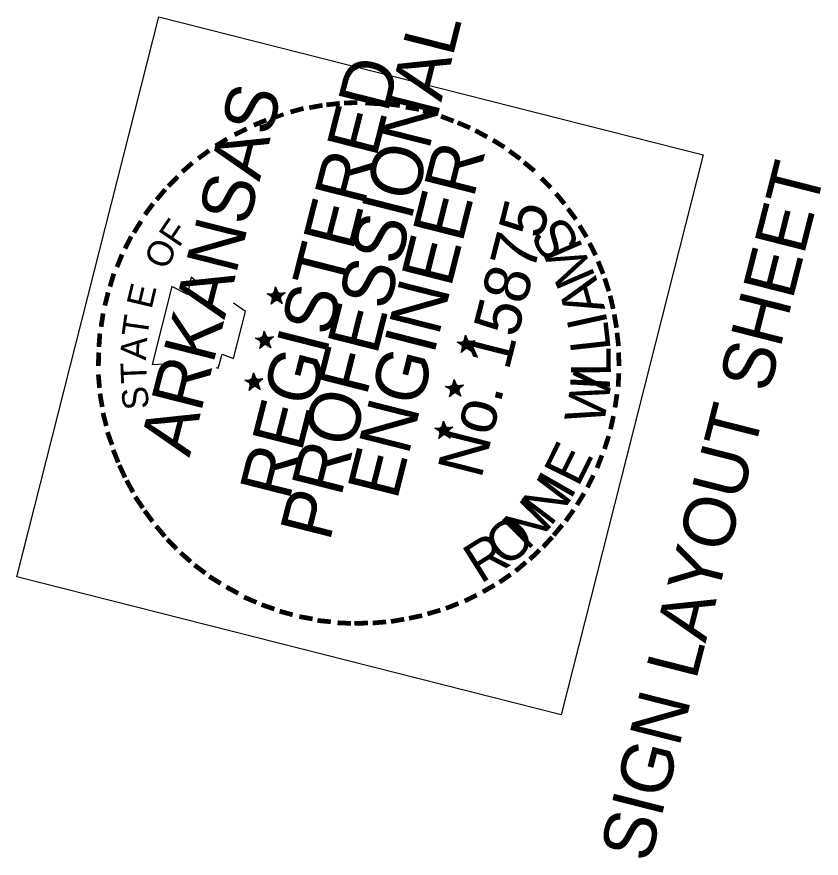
# Model space of a CAD drawing. Extents: x 670002 to 670131, y 737835 to 738002.
# Drawn here: x 670111.64 to 670131.06, y 737963.5 to 737983.82 of the extents above; entities that cross this region are included whole.
import ezdxf

# ---------------------------------------------------------------- set-up
doc = ezdxf.new("R2010")
doc.units = 0
for name, color, linetype in [('R_Border Notes', 7, 'Continuous'), ('R_Border PE', 7, 'Continuous'), ('R_Border Prem', 7, 'Continuous')]:
    doc.layers.add(name, color=color, linetype=linetype)

msp = doc.modelspace()

# ---------------------------------------------------------------- linework, layer by layer
at = {"layer": 'R_Border PE'}
for p, q in [((670117.891, 737977.302), (670117.856, 737977.111)), ((670117.891, 737977.302), (670117.877, 737977.119)), ((670117.891, 737977.302), (670117.889, 737977.116)), ((670117.891, 737977.302), (670117.904, 737977.073)), ((670117.891, 737977.302), (670117.912, 737977.155)), ((670117.891, 737977.302), (670117.92, 737977.159)), ((670117.891, 737977.302), (670117.929, 737977.17)), ((670117.686, 737977.128), (670117.848, 737977.132)), ((670117.904, 737977.073), (670117.686, 737977.128)), ((670117.686, 737977.128), (670117.845, 737977.12)), ((670117.686, 737977.128), (670117.834, 737977.104)), ((670117.686, 737977.128), (670117.834, 737977.078)), ((670117.686, 737977.128), (670117.831, 737977.066)), ((670117.686, 737977.128), (670117.822, 737977.055)), ((670117.784, 737976.878), (670117.904, 737977.073)), ((670118.118, 737977.154), (670117.904, 737977.073)), ((670118.052, 737976.894), (670117.904, 737977.073)), ((670118.118, 737977.154), (670117.922, 737977.12)), ((670118.118, 737977.154), (670117.926, 737977.132)), ((670118.118, 737977.154), (670117.945, 737977.108)), ((670118.118, 737977.154), (670117.953, 737977.061)), ((670118.052, 737976.894), (670117.953, 737977.061)), ((670118.118, 737977.154), (670117.965, 737977.083)), ((670118.118, 737977.154), (670117.971, 737977.056)), ((670118.052, 737976.894), (670117.972, 737977.062)), ((670117.784, 737976.878), (670117.842, 737977.031)), ((670117.784, 737976.878), (670117.852, 737977.022)), ((670117.784, 737976.878), (670117.858, 737977.02)), ((670117.784, 737976.878), (670117.881, 737977.008)), ((670117.784, 737976.878), (670117.893, 737977.005)), ((670117.784, 737976.878), (670117.905, 737977.002)), ((670118.052, 737976.894), (670117.901, 737977.009)), ((670118.052, 737976.894), (670117.921, 737977.011)), ((670118.052, 737976.894), (670117.93, 737977.021)), ((670118.052, 737976.894), (670117.952, 737977.035)), ((670117.402, 737976.059), (670117.57, 737976.062)), ((670117.626, 737976.002), (670117.402, 737976.059)), ((670117.402, 737976.059), (670117.561, 737976.051)), ((670117.402, 737976.059), (670117.556, 737976.033)), ((670117.402, 737976.059), (670117.55, 737976.009)), ((670117.402, 737976.059), (670117.553, 737975.995)), ((670117.402, 737976.059), (670117.546, 737975.99)), ((670117.613, 737976.231), (670117.578, 737976.04)), ((670117.613, 737976.231), (670117.599, 737976.048)), ((670117.613, 737976.231), (670117.611, 737976.045)), ((670117.613, 737976.231), (670117.626, 737976.002)), ((670117.613, 737976.231), (670117.634, 737976.084)), ((670117.613, 737976.231), (670117.643, 737976.095)), ((670117.613, 737976.231), (670117.651, 737976.099)), ((670117.842, 737976.089), (670117.626, 737976.002)), ((670117.842, 737976.089), (670117.641, 737976.063)), ((670117.842, 737976.089), (670117.644, 737976.049)), ((670117.842, 737976.089), (670117.667, 737976.037)), ((670117.842, 737976.089), (670117.675, 737975.99)), ((670117.842, 737976.089), (670117.687, 737976.013)), ((670117.842, 737976.089), (670117.693, 737975.985)), ((670122.476, 737976.133), (670122.442, 737975.948)), ((670122.476, 737976.133), (670122.463, 737975.955)), ((670122.476, 737976.133), (670122.475, 737975.952)), ((670122.476, 737976.133), (670122.49, 737975.91)), ((670122.476, 737976.133), (670122.496, 737975.986)), ((670122.476, 737976.133), (670122.512, 737975.995)), ((670122.476, 737976.133), (670122.519, 737975.999)), ((670117.506, 737975.807), (670117.626, 737976.002)), ((670117.506, 737975.807), (670117.558, 737975.962)), ((670117.506, 737975.807), (670117.57, 737975.959)), ((670117.506, 737975.807), (670117.58, 737975.949)), ((670117.506, 737975.807), (670117.603, 737975.937)), ((670117.506, 737975.807), (670117.615, 737975.934)), ((670117.506, 737975.807), (670117.627, 737975.931)), ((670117.776, 737975.829), (670117.623, 737975.939)), ((670117.776, 737975.829), (670117.626, 737976.002)), ((670117.776, 737975.829), (670117.643, 737975.94)), ((670117.776, 737975.829), (670117.652, 737975.951)), ((670117.776, 737975.829), (670117.674, 737975.964)), ((670117.776, 737975.829), (670117.675, 737975.99)), ((670117.776, 737975.829), (670117.694, 737975.991)), ((670122.49, 737975.91), (670122.272, 737975.965)), ((670122.272, 737975.965), (670122.433, 737975.963)), ((670122.272, 737975.965), (670122.431, 737975.957)), ((670122.272, 737975.965), (670122.427, 737975.939)), ((670122.272, 737975.965), (670122.42, 737975.915)), ((670122.272, 737975.965), (670122.417, 737975.903)), ((670122.272, 737975.965), (670122.414, 737975.89)), ((670122.37, 737975.715), (670122.49, 737975.91)), ((670122.37, 737975.715), (670122.426, 737975.862)), ((670122.37, 737975.715), (670122.438, 737975.859)), ((670122.37, 737975.715), (670122.449, 737975.849)), ((670122.37, 737975.715), (670122.467, 737975.845)), ((670122.638, 737975.731), (670122.485, 737975.84)), ((670122.704, 737975.991), (670122.49, 737975.91)), ((670122.638, 737975.731), (670122.49, 737975.91)), ((670122.704, 737975.991), (670122.507, 737975.951)), ((670122.704, 737975.991), (670122.51, 737975.963)), ((670122.638, 737975.731), (670122.511, 737975.84)), ((670122.638, 737975.731), (670122.522, 737975.857)), ((670122.704, 737975.991), (670122.536, 737975.937)), ((670122.638, 737975.731), (670122.539, 737975.872)), ((670122.704, 737975.991), (670122.543, 737975.89)), ((670122.638, 737975.731), (670122.543, 737975.89)), ((670122.704, 737975.991), (670122.549, 737975.914)), ((670122.638, 737975.731), (670122.557, 737975.893)), ((670122.704, 737975.991), (670122.561, 737975.885)), ((670122.37, 737975.715), (670122.484, 737975.834)), ((670122.37, 737975.715), (670122.496, 737975.831)), ((670117.145, 737975.047), (670117.314, 737975.05)), ((670117.369, 737974.991), (670117.145, 737975.047)), ((670117.145, 737975.047), (670117.304, 737975.039)), ((670117.145, 737975.047), (670117.301, 737975.027)), ((670117.145, 737975.047), (670117.295, 737975.003)), ((670117.145, 737975.047), (670117.297, 737974.983)), ((670117.145, 737975.047), (670117.289, 737974.979)), ((670117.357, 737975.22), (670117.321, 737975.029)), ((670117.357, 737975.22), (670117.342, 737975.036)), ((670117.357, 737975.22), (670117.354, 737975.033)), ((670117.357, 737975.22), (670117.369, 737974.991)), ((670117.357, 737975.22), (670117.377, 737975.072)), ((670117.357, 737975.22), (670117.386, 737975.083)), ((670117.357, 737975.22), (670117.394, 737975.088)), ((670117.585, 737975.078), (670117.369, 737974.991)), ((670117.585, 737975.078), (670117.385, 737975.051)), ((670117.585, 737975.078), (670117.388, 737975.038)), ((670117.585, 737975.078), (670117.411, 737975.025)), ((670117.585, 737975.078), (670117.418, 737974.978)), ((670117.585, 737975.078), (670117.43, 737975.001)), ((670117.585, 737975.078), (670117.436, 737974.974)), ((670122.198, 737975.062), (670122.164, 737974.877)), ((670122.198, 737975.062), (670122.185, 737974.885)), ((670122.198, 737975.062), (670122.197, 737974.882)), ((670122.198, 737975.062), (670122.212, 737974.839)), ((670122.198, 737975.062), (670122.218, 737974.915)), ((670122.198, 737975.062), (670122.228, 737974.926)), ((670122.198, 737975.062), (670122.243, 737974.935)), ((670117.249, 737974.795), (670117.369, 737974.991)), ((670117.249, 737974.795), (670117.301, 737974.95)), ((670117.249, 737974.795), (670117.313, 737974.947)), ((670117.249, 737974.795), (670117.324, 737974.938)), ((670117.249, 737974.795), (670117.348, 737974.932)), ((670117.249, 737974.795), (670117.359, 737974.922)), ((670117.249, 737974.795), (670117.371, 737974.919)), ((670117.519, 737974.817), (670117.366, 737974.927)), ((670117.519, 737974.817), (670117.369, 737974.991)), ((670117.519, 737974.817), (670117.386, 737974.928)), ((670117.519, 737974.817), (670117.395, 737974.939)), ((670117.519, 737974.817), (670117.418, 737974.978)), ((670117.519, 737974.817), (670117.418, 737974.953)), ((670117.519, 737974.817), (670117.438, 737974.98)), ((670122.212, 737974.839), (670121.994, 737974.894)), ((670121.994, 737974.894), (670122.155, 737974.892)), ((670121.994, 737974.894), (670122.153, 737974.886)), ((670121.994, 737974.894), (670122.149, 737974.868)), ((670121.994, 737974.894), (670122.142, 737974.844)), ((670121.994, 737974.894), (670122.139, 737974.832)), ((670121.994, 737974.894), (670122.13, 737974.821)), ((670122.092, 737974.644), (670122.212, 737974.839)), ((670122.426, 737974.92), (670122.212, 737974.839)), ((670122.36, 737974.66), (670122.212, 737974.839)), ((670122.426, 737974.92), (670122.229, 737974.88)), ((670122.426, 737974.92), (670122.234, 737974.898)), ((670122.426, 737974.92), (670122.253, 737974.874)), ((670122.36, 737974.66), (670122.261, 737974.827)), ((670122.426, 737974.92), (670122.267, 737974.825)), ((670122.426, 737974.92), (670122.271, 737974.844)), ((670122.426, 737974.92), (670122.277, 737974.816)), ((670122.36, 737974.66), (670122.279, 737974.822)), ((670122.092, 737974.644), (670122.148, 737974.791)), ((670122.092, 737974.644), (670122.16, 737974.788)), ((670122.092, 737974.644), (670122.166, 737974.786)), ((670122.092, 737974.644), (670122.189, 737974.774)), ((670122.092, 737974.644), (670122.201, 737974.771)), ((670122.092, 737974.644), (670122.213, 737974.768)), ((670122.36, 737974.66), (670122.209, 737974.776)), ((670122.36, 737974.66), (670122.235, 737974.775)), ((670122.36, 737974.66), (670122.244, 737974.786)), ((670122.36, 737974.66), (670122.26, 737974.801)), ((670121.943, 737974.056), (670121.907, 737973.866)), ((670121.943, 737974.056), (670121.928, 737973.873)), ((670121.943, 737974.056), (670121.941, 737973.87)), ((670121.943, 737974.056), (670121.956, 737973.827)), ((670121.943, 737974.056), (670121.962, 737973.903)), ((670121.943, 737974.056), (670121.971, 737973.914)), ((670121.943, 737974.056), (670121.986, 737973.923)), ((670121.737, 737973.883), (670121.9, 737973.887)), ((670121.956, 737973.827), (670121.737, 737973.883)), ((670121.737, 737973.883), (670121.897, 737973.875)), ((670121.737, 737973.883), (670121.892, 737973.856)), ((670121.737, 737973.883), (670121.886, 737973.832)), ((670121.737, 737973.883), (670121.883, 737973.82)), ((670121.737, 737973.883), (670121.874, 737973.81)), ((670121.835, 737973.632), (670121.956, 737973.827)), ((670122.17, 737973.909), (670121.956, 737973.827)), ((670122.103, 737973.648), (670121.956, 737973.827)), ((670122.17, 737973.909), (670121.972, 737973.868)), ((670122.17, 737973.909), (670121.977, 737973.886)), ((670122.17, 737973.909), (670121.997, 737973.862)), ((670122.103, 737973.648), (670122.004, 737973.815)), ((670122.17, 737973.909), (670122.01, 737973.814)), ((670122.17, 737973.909), (670122.015, 737973.832)), ((670122.17, 737973.909), (670122.021, 737973.804)), ((670122.103, 737973.648), (670122.022, 737973.811)), ((670121.835, 737973.632), (670121.893, 737973.785)), ((670121.835, 737973.632), (670121.904, 737973.776)), ((670121.835, 737973.632), (670121.91, 737973.775)), ((670121.835, 737973.632), (670121.933, 737973.762)), ((670121.835, 737973.632), (670121.945, 737973.759)), ((670121.835, 737973.632), (670121.957, 737973.756)), ((670122.103, 737973.648), (670121.952, 737973.764)), ((670122.103, 737973.648), (670121.978, 737973.764)), ((670122.103, 737973.648), (670121.987, 737973.774)), ((670122.103, 737973.648), (670122.004, 737973.789))]:
    msp.add_line(p, q, dxfattribs=at)
for points in [[(670116.003, 737977.407), (670115.855, 737977.535), (670115.761, 737977.114), (670115.384, 737977.306), (670114.906, 737975.422)], [(670117.686, 737977.128), (670118.118, 737977.154), (670117.784, 737976.878), (670117.891, 737977.302), (670118.052, 737976.894), (670117.686, 737977.128)], [(670116.448, 737975.347), (670116.502, 737975.333), (670116.6, 737975.669), (670116.877, 737975.567), (670117.165, 737976.7), (670116.874, 737976.902)], [(670117.402, 737976.059), (670117.842, 737976.089), (670117.506, 737975.807), (670117.613, 737976.231), (670117.776, 737975.829), (670117.402, 737976.059)], [(670122.272, 737975.965), (670122.704, 737975.991), (670122.37, 737975.715), (670122.476, 737976.133), (670122.638, 737975.731), (670122.272, 737975.965)], [(670114.906, 737975.422), (670115.449, 737975.452)], [(670117.145, 737975.047), (670117.585, 737975.078), (670117.249, 737974.795), (670117.357, 737975.22), (670117.519, 737974.817), (670117.145, 737975.047)], [(670121.994, 737974.894), (670122.426, 737974.92), (670122.092, 737974.644), (670122.198, 737975.062), (670122.36, 737974.66), (670121.994, 737974.894)], [(670121.737, 737973.883), (670122.17, 737973.909), (670121.835, 737973.632), (670121.943, 737974.056), (670122.103, 737973.648), (670121.737, 737973.883)]]:
    msp.add_lwpolyline(points, dxfattribs=at)
for centre, radius in [((670117.905, 737977.072), 0.108), ((670117.905, 737977.072), 0.0975), ((670117.905, 737977.072), 0.0904), ((670117.905, 737977.072), 0.083), ((670117.905, 737977.072), 0.0723), ((670117.905, 737977.072), 0.0672), ((670117.905, 737977.072), 0.0619), ((670117.905, 737977.072), 0.0533), ((670117.905, 737977.072), 0.0467), ((670117.905, 737977.072), 0.0388), ((670117.905, 737977.072), 0.031), ((670117.905, 737977.072), 0.0231), ((670117.905, 737977.072), 0.0185), ((670117.905, 737977.072), 0.00901), ((670117.627, 737976.003), 0.108), ((670117.627, 737976.003), 0.0975), ((670117.627, 737976.003), 0.0904), ((670117.627, 737976.003), 0.083), ((670117.627, 737976.003), 0.0723), ((670117.627, 737976.003), 0.0672), ((670117.627, 737976.003), 0.0619), ((670117.627, 737976.003), 0.0533), ((670117.627, 737976.003), 0.0467), ((670117.627, 737976.003), 0.0388), ((670117.627, 737976.003), 0.031), ((670117.627, 737976.003), 0.0231), ((670117.627, 737976.003), 0.0185), ((670117.627, 737976.003), 0.00901), ((670122.493, 737975.906), 0.108), ((670122.493, 737975.906), 0.0975), ((670122.493, 737975.906), 0.0904), ((670122.493, 737975.906), 0.083), ((670122.493, 737975.906), 0.0723), ((670122.493, 737975.906), 0.0672), ((670122.493, 737975.906), 0.0619), ((670122.493, 737975.906), 0.0533), ((670122.493, 737975.906), 0.0467), ((670122.493, 737975.906), 0.0388), ((670122.493, 737975.906), 0.031), ((670122.493, 737975.906), 0.0231), ((670122.493, 737975.906), 0.0185), ((670122.493, 737975.906), 0.00901), ((670117.37, 737974.992), 0.108), ((670117.37, 737974.992), 0.0975), ((670117.37, 737974.992), 0.0904), ((670117.37, 737974.992), 0.083), ((670117.37, 737974.992), 0.0723), ((670117.37, 737974.992), 0.0672), ((670117.37, 737974.992), 0.0619), ((670117.37, 737974.992), 0.0533), ((670117.37, 737974.992), 0.0467), ((670117.37, 737974.992), 0.0388), ((670117.37, 737974.992), 0.031), ((670117.37, 737974.992), 0.0231), ((670117.37, 737974.992), 0.0185), ((670117.37, 737974.992), 0.00901), ((670122.214, 737974.837), 0.108), ((670122.214, 737974.837), 0.0975), ((670122.214, 737974.837), 0.0904), ((670122.214, 737974.837), 0.083), ((670122.214, 737974.837), 0.0723), ((670122.214, 737974.837), 0.0672), ((670122.214, 737974.837), 0.0619), ((670122.214, 737974.837), 0.0533), ((670122.214, 737974.837), 0.0467), ((670122.214, 737974.837), 0.0388), ((670122.214, 737974.837), 0.031), ((670122.214, 737974.837), 0.0231), ((670122.214, 737974.837), 0.0185), ((670122.214, 737974.837), 0.00901), ((670121.958, 737973.826), 0.108), ((670121.958, 737973.826), 0.0975), ((670121.958, 737973.826), 0.0904), ((670121.958, 737973.826), 0.083), ((670121.958, 737973.826), 0.0723), ((670121.958, 737973.826), 0.0672), ((670121.958, 737973.826), 0.0619), ((670121.958, 737973.826), 0.0533), ((670121.958, 737973.826), 0.0467), ((670121.958, 737973.826), 0.0388), ((670121.958, 737973.826), 0.031), ((670121.958, 737973.826), 0.0231), ((670121.958, 737973.826), 0.0185), ((670121.958, 737973.826), 0.00901)]:
    msp.add_circle(centre, radius, dxfattribs=at)
at = {"layer": 'R_Border Prem'}
msp.add_lwpolyline([(670111.642, 737970.298), (670115.071, 737983.82), (670128.217, 737980.485), (670124.788, 737966.964)], close=True, dxfattribs=at)

# ---------------------------------------------------------------- texts
at = {"layer": 'R_Border Notes'}
msp.add_text('SIGN LAYOUT SHEET', height=1.25, rotation=75.7686, dxfattribs=at).set_placement((670126.923, 737963.367))
at = {"layer": 'R_Border PE'}
for s, height, rotation, p in [('PROFESSIONAL', 1.24999, 75.7686, (670119.194, 737971.123)), ('REGISTERED', 1.25, 75.7686, (670118.219, 737972.112)), ('ARKANSAS', 1.25, 75.7686, (670115.809, 737973.162)), ('-', 1, 10.4313, (670118.714, 737981.233)), ('-', 1, 6.3414, (670119.099, 737981.303)), ('-', 1, 0.8918, (670119.486, 737981.353)), ('-', 1, 356.3179, (670119.971, 737981.359)), ('-', 1, 352.3647, (670120.458, 737981.345)), ('-', 1, 15.4369, (670118.295, 737981.133)), ('-', 1, 350.0987, (670120.909, 737981.269)), ('-', 1, 345.7092, (670121.295, 737981.191)), ('-', 1, 22.4207, (670117.456, 737980.823)), ('-', 0.875, 19.4438, (670117.877, 737981.033)), ('-', 1, 339.2857, (670121.692, 737981.077)), ('-', 1, 25.6483, (670117.013, 737980.6)), ('-', 1, 336.7638, (670122.081, 737980.933)), ('-', 1, 331.5312, (670122.476, 737980.762)), ('-', 1, 31.3471, (670116.592, 737980.34)), ('ENGINEER', 1.25, 75.7686, (670120.82, 737972.123)), ('-', 1, 328.6366, (670122.885, 737980.543)), ('-', 1, 36.2983, (670116.203, 737980.051)), ('-', 1, 323.6572, (670123.257, 737980.306)), ('-', 1, 41.6312, (670115.849, 737979.748)), ('-', 1, 320.3883, (670123.597, 737980.046)), ('-', 1, 45.4094, (670115.532, 737979.416)), ('-', 1, 314.8398, (670123.992, 737979.694)), ('-', 1, 49.8896, (670115.273, 737979.107)), ('-', 1, 309.6138, (670124.324, 737979.352)), ('-', 1, 53.6236, (670115.013, 737978.767)), ('No. 15875', 1.1, 75.7686, (670122.853, 737972.638)), ('-', 1, 307.0223, (670124.603, 737979.004)), ('-', 1, 58.1047, (670114.766, 737978.353)), ('F', 0.625, 55.8392, (670115.552, 737978.224)), ('S', 0.962, 121.462, (670125.276, 737978.325)), ('-', 1, 301.5339, (670124.869, 737978.627)), ('-', 1, 62.9734, (670114.572, 737977.995)), ('O', 0.625, 66.2201, (670115.267, 737977.684)), ('M', 0.962, 113.3256, (670125.628, 737977.536)), ('-', 1, 296.8536, (670125.098, 737978.234)), ('-', 1, 67.9303, (670114.395, 737977.576)), ('-', 1, 291.5049, (670125.298, 737977.829)), ('-', 1, 73.5116, (670114.245, 737977.137)), ('A', 0.962, 105.7601, (670125.852, 737976.763)), ('-', 1, 288.0176, (670125.451, 737977.441)), ('E', 0.625, 76.6009, (670114.892, 737976.741)), ('-', 1, 75.9548, (670114.127, 737976.696)), ('-', 1, 283.1254, (670125.579, 737977.054)), ('-', 1, 81.6654, (670114.051, 737976.219)), ('T', 0.625, 81.7913, (670114.79, 737976.057)), ('I', 0.962, 102.3343, (670125.92, 737976.405)), ('-', 1, 280.0202, (670125.676, 737976.624)), ('L', 0.962, 96.339, (670125.986, 737975.772)), ('-', 1, 85.9879, (670114.005, 737975.76)), ('A', 0.625, 86.9817, (670114.762, 737975.516)), ('-', 1, 276.487, (670125.744, 737976.207)), ('-', 1, 89.3987, (670113.998, 737975.323)), ('L', 0.962, 90.3438, (670125.986, 737975.134)), ('-', 1, 271.2428, (670125.787, 737975.764)), ('T', 0.625, 92.1721, (670114.786, 737974.975)), ('W', 0.962, 78.7816, (670125.799, 737973.921)), ('-', 1, 94.9446, (670114.028, 737974.832)), ('I', 0.962, 86.9179, (670125.956, 737974.771)), ('-', 1, 267.0543, (670125.796, 737975.291)), ('S', 0.625, 97.3626, (670114.846, 737974.373)), ('-', 1, 100.0758, (670114.095, 737974.409)), ('-', 1, 261.5852, (670125.761, 737974.823)), ('-', 1, 104.5604, (670114.192, 737973.978)), ('-', 1, 257.3603, (670125.685, 737974.32)), ('-', 1, 109.8321, (670114.324, 737973.558)), ('-', 1, 252.2868, (670125.583, 737973.868)), ('E', 0.962, 63.7221, (670125.198, 737972.441)), ('-', 1, 112.0003, (670114.471, 737973.147)), ('-', 1, 248.884, (670125.432, 737973.423)), ('-', 1, 114.7192, (670114.629, 737972.803)), ('I', 0.962, 60.2962, (670125.008, 737972.13)), ('-', 1, 118.7308, (670114.816, 737972.472)), ('N', 0.962, 52.7308, (670124.526, 737971.487)), ('-', 1, 243.3241, (670125.247, 737972.973)), ('-', 1, 124.1916, (670115.037, 737972.126)), ('-', 1, 238.5668, (670125.039, 737972.562)), ('N', 0.962, 45.1654, (670123.964, 737970.912)), ('-', 1, 126.3827, (670115.267, 737971.81)), ('-', 1, 234.3298, (670124.807, 737972.182)), ('O', 0.962, 38.8847, (670123.442, 737970.495)), ('-', 1, 230.3687, (670124.553, 737971.84)), ('-', 1, 130.001, (670115.549, 737971.474)), ('-', 1, 133.8392, (670115.819, 737971.193)), ('R', 0.962, 32.1757, (670122.839, 737970.115)), ('-', 1, 227.3389, (670124.328, 737971.562)), ('-', 1, 223.8583, (670124.039, 737971.262)), ('-', 1, 138.6399, (670116.141, 737970.911)), ('-', 1, 143.5428, (670116.471, 737970.66)), ('-', 1, 220.4149, (670123.728, 737970.979)), ('-', 1, 148.163, (670116.819, 737970.43)), ('-', 1, 214.7024, (670123.394, 737970.703)), ('-', 1, 151.2295, (670117.226, 737970.204)), ('-', 1, 209.9924, (670123.035, 737970.459)), ('-', 1, 156.9698, (670117.634, 737970.01)), ('-', 1, 206.4867, (670122.628, 737970.227)), ('-', 1, 160.9549, (670118.042, 737969.862)), ('-', 1, 196.2157, (670121.818, 737969.878)), ('-', 1, 201.662, (670122.218, 737970.034)), ('-', 1, 164.8308, (670118.461, 737969.736)), ('-', 1, 169.9644, (670118.91, 737969.648)), ('-', 1, 191.4974, (670121.411, 737969.749)), ('-', 1, 174.7165, (670119.32, 737969.589)), ('-', 1, 177.4835, (670119.788, 737969.554)), ('-', 1, 181.2264, (670120.172, 737969.566)), ('-', 1, 184.856, (670120.586, 737969.597)), ('-', 1, 189.8329, (670120.989, 737969.662))]:
    msp.add_text(s, height=height, rotation=rotation, dxfattribs=at).set_placement(p)

doc.saveas('drawing.dxf')
